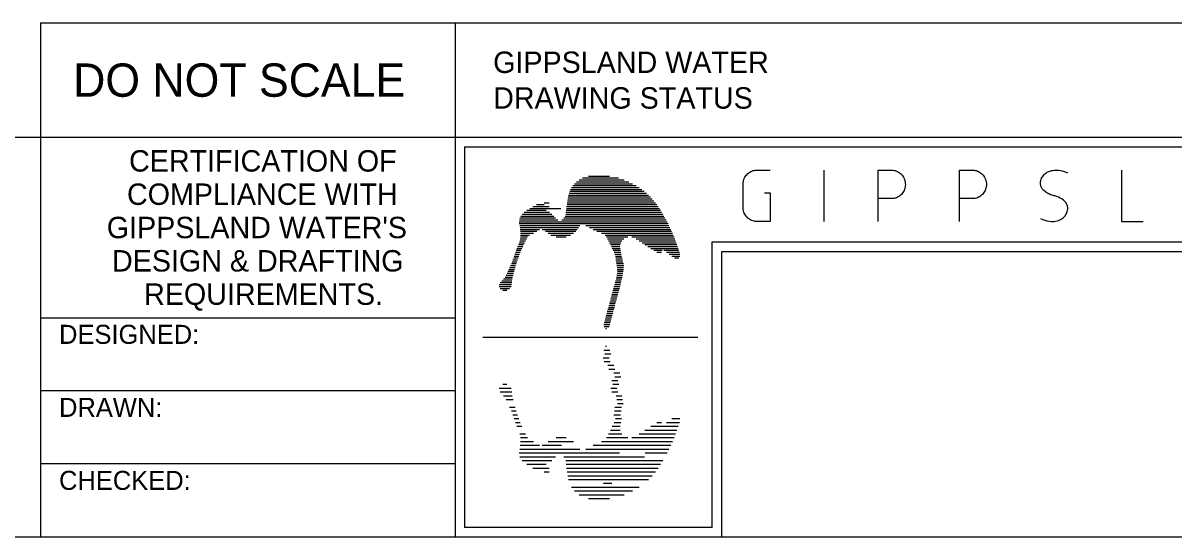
# Model space of a CAD drawing. Extents: x 0 to 841, y 0 to 594.
# Drawn here: x 590.7 to 711.5, y 15 to 69 of the extents above; entities that cross this region are included whole.
import ezdxf

# ---------------------------------------------------------------- set-up
doc = ezdxf.new("R2010")
doc.units = 0
doc.layers.add('A1BORDER', color=7, linetype='Continuous')

msp = doc.modelspace()

# ---------------------------------------------------------------- linework, layer by layer
at = {"layer": 'A1BORDER'}
for p, q in [((592.5, 69), (592.5, 15)), ((592.5, 69), (829, 69)), ((636, 69), (636, 15)), ((28, 57), (829, 57)), ((637, 56), (788, 56)), ((637, 56), (637, 16)), ((648.53, 52.12), (654.64, 52.12)), ((648.74, 52.32), (654.24, 52.32)), ((649.02, 52.52), (653.76, 52.52)), ((649.39, 52.72), (653.15, 52.72)), ((650.01, 52.92), (652.2, 52.92)), ((647.91, 50.92), (656.3, 50.92)), ((647.96, 51.12), (656.08, 51.12)), ((648.03, 51.32), (655.85, 51.32)), ((648.12, 51.52), (655.59, 51.52)), ((648.23, 51.72), (655.31, 51.72)), ((648.37, 51.92), (655, 51.92)), ((644.18, 49.72), (645.89, 49.72)), ((644.54, 49.92), (645.36, 49.92)), ((645.37, 50.12), (645.86, 50.12)), ((647.71, 49.72), (657.31, 49.72)), ((647.75, 49.92), (657.17, 49.92)), ((647.78, 50.12), (657.02, 50.12)), ((647.81, 50.32), (656.86, 50.32)), ((647.85, 50.52), (656.69, 50.52)), ((647.88, 50.72), (656.5, 50.72)), ((642.75, 48.32), (646.79, 48.32)), ((642.81, 48.52), (646.55, 48.52)), ((642.9, 48.72), (646.37, 48.72)), ((643.04, 48.92), (646.16, 48.92)), ((643.26, 49.12), (645.9, 49.12)), ((643.54, 49.32), (645.57, 49.32)), ((643.85, 49.52), (647.09, 49.52)), ((647.19, 48.32), (658.14, 48.32)), ((647.42, 48.52), (658.03, 48.52)), ((647.54, 48.72), (657.92, 48.72)), ((647.61, 48.92), (657.8, 48.92)), ((647.63, 49.12), (657.68, 49.12)), ((647.66, 49.32), (657.57, 49.32)), ((647.69, 49.52), (657.44, 49.52)), ((642.73, 48.12), (658.25, 48.12)), ((642.74, 47.92), (658.35, 47.92)), ((642.79, 47.72), (649.08, 47.72)), ((642.83, 47.52), (648.95, 47.52)), ((642.85, 47.31), (644.88, 47.31)), ((642.87, 47.12), (644.57, 47.12)), ((645.14, 47.31), (648.83, 47.31)), ((645.49, 47.12), (648.67, 47.12)), ((649.72, 47.72), (658.45, 47.72)), ((650.12, 47.52), (658.55, 47.52)), ((650.48, 47.31), (658.64, 47.31)), ((650.87, 47.12), (658.73, 47.12)), ((642.72, 45.92), (643.3, 45.92)), ((642.79, 46.12), (643.4, 46.12)), ((642.84, 46.32), (643.5, 46.32)), ((642.87, 46.52), (643.6, 46.52)), ((642.88, 46.92), (644.23, 46.92)), ((642.88, 46.72), (643.83, 46.72)), ((645.76, 46.92), (648.42, 46.92)), ((646.05, 46.72), (648.11, 46.72)), ((646.62, 46.52), (647.67, 46.52)), ((651.36, 46.92), (658.82, 46.92)), ((651.76, 46.72), (658.9, 46.72)), ((651.88, 46.52), (654.15, 46.52)), ((651.99, 46.32), (653.71, 46.32)), ((652.1, 46.12), (653.52, 46.12)), ((652.2, 45.92), (653.4, 45.92)), ((654.57, 46.52), (658.99, 46.52)), ((655, 46.32), (659.07, 46.32)), ((655.31, 46.12), (659.14, 46.12)), ((655.62, 45.92), (659.22, 45.92)), ((663, 46), (788, 46)), ((663, 16), (663, 46)), ((642.28, 44.72), (642.76, 44.72)), ((642.35, 44.92), (642.83, 44.92)), ((642.43, 45.12), (642.9, 45.12)), ((642.5, 45.32), (643, 45.32)), ((642.57, 45.52), (643.1, 45.52)), ((642.65, 45.72), (643.2, 45.72)), ((652.31, 45.72), (653.33, 45.72)), ((652.41, 45.52), (653.31, 45.52)), ((652.5, 45.32), (653.34, 45.32)), ((652.6, 45.12), (653.38, 45.12)), ((652.69, 44.92), (653.41, 44.92)), ((652.78, 44.72), (653.44, 44.72)), ((655.93, 45.72), (659.29, 45.72)), ((656.24, 45.52), (659.35, 45.52)), ((656.55, 45.32), (659.42, 45.32)), ((656.86, 45.12), (657.74, 45.12)), ((657.17, 44.92), (657.68, 44.92)), ((657.51, 44.72), (657.54, 44.72)), ((657.91, 45.12), (659.48, 45.12)), ((658.19, 44.92), (659.54, 44.92)), ((658.47, 44.72), (659.59, 44.72)), ((664, 45), (829, 45)), ((664, 15), (664, 45)), ((641.82, 43.51), (642.35, 43.51)), ((641.91, 43.72), (642.41, 43.72)), ((641.99, 43.92), (642.48, 43.92)), ((642.06, 44.12), (642.55, 44.12)), ((642.13, 44.32), (642.62, 44.32)), ((642.21, 44.52), (642.69, 44.52)), ((652.83, 44.52), (653.48, 44.52)), ((652.86, 44.32), (653.53, 44.32)), ((652.89, 44.12), (653.57, 44.12)), ((652.91, 43.92), (653.62, 43.92)), ((652.94, 43.72), (653.67, 43.72)), ((652.97, 43.51), (653.71, 43.51)), ((658.75, 44.52), (659.58, 44.52)), ((659.02, 44.32), (659.47, 44.32)), ((641.25, 42.31), (642.04, 42.31)), ((641.37, 42.52), (642.09, 42.52)), ((641.46, 42.72), (642.15, 42.72)), ((641.55, 42.92), (642.2, 42.92)), ((641.64, 43.12), (642.25, 43.12)), ((641.73, 43.32), (642.3, 43.32)), ((652.95, 42.31), (653.53, 42.31)), ((652.99, 42.52), (653.57, 42.52)), ((653, 43.32), (653.69, 43.32)), ((653.02, 43.12), (653.67, 43.12)), ((653.03, 42.72), (653.61, 42.72)), ((653.05, 42.92), (653.64, 42.92)), ((640.62, 41.32), (641.88, 41.32)), ((640.63, 41.52), (641.93, 41.52)), ((640.72, 41.12), (641.73, 41.12)), ((640.73, 41.72), (641.95, 41.72)), ((640.9, 41.92), (641.97, 41.92)), ((641.1, 42.12), (642, 42.12)), ((652.63, 41.12), (653.26, 41.12)), ((652.68, 41.32), (653.31, 41.32)), ((652.74, 41.52), (653.37, 41.52)), ((652.79, 41.72), (653.41, 41.72)), ((652.85, 41.92), (653.45, 41.92)), ((652.9, 42.12), (653.49, 42.12)), ((641.03, 40.92), (641.43, 40.92)), ((652.3, 39.92), (652.93, 39.92)), ((652.36, 40.12), (652.99, 40.12)), ((652.41, 40.32), (653.04, 40.32)), ((652.47, 40.52), (653.1, 40.52)), ((652.52, 40.72), (653.15, 40.72)), ((652.57, 40.92), (653.2, 40.92)), ((651.98, 38.72), (652.61, 38.72)), ((652.03, 38.92), (652.66, 38.92)), ((652.09, 39.12), (652.72, 39.12)), ((652.14, 39.32), (652.77, 39.32)), ((652.2, 39.52), (652.82, 39.52)), ((652.25, 39.72), (652.88, 39.72)), ((636, 38), (592.5, 38)), ((651.65, 37.52), (652.28, 37.52)), ((651.71, 37.72), (652.34, 37.72)), ((651.76, 37.92), (652.39, 37.92)), ((651.82, 38.12), (652.44, 38.12)), ((651.87, 38.32), (652.5, 38.32)), ((651.92, 38.52), (652.55, 38.52)), ((651.63, 37.32), (652.23, 37.32)), ((651.64, 37.12), (652.17, 37.12)), ((651.79, 36.92), (651.9, 36.92)), ((638.93, 35.98), (661.47, 35.98)), ((651.79, 35.04), (651.9, 35.04)), ((651.54, 33.84), (652.17, 33.84)), ((651.63, 34.64), (652.23, 34.64)), ((651.71, 34.24), (652.34, 34.24)), ((651.65, 33.44), (652.28, 33.44)), ((652.03, 33.04), (652.66, 33.04)), ((652.14, 32.64), (652.77, 32.64)), ((652.47, 31.44), (653.1, 31.44)), ((652.66, 32.24), (653.29, 32.24)), ((652.77, 31.84), (653.4, 31.84)), ((636, 30.34), (592.5, 30.34)), ((640.62, 30.64), (641.88, 30.64)), ((640.73, 30.24), (641.95, 30.24)), ((641.03, 31.04), (641.43, 31.04)), ((652.34, 30.64), (652.97, 30.64)), ((652.45, 30.24), (653.07, 30.24)), ((652.57, 31.04), (653.2, 31.04)), ((641.1, 29.84), (642, 29.84)), ((641.37, 29.44), (642.09, 29.44)), ((652.9, 29.84), (653.49, 29.84)), ((652.99, 29.44), (653.57, 29.44)), ((653.05, 29.04), (653.64, 29.04)), ((641.73, 28.64), (642.3, 28.64)), ((641.91, 28.24), (642.41, 28.24)), ((642.06, 27.84), (642.55, 27.84)), ((652.66, 27.84), (653.35, 27.84)), ((652.72, 28.24), (653.44, 28.24)), ((652.77, 28.64), (653.46, 28.64)), ((642.21, 27.44), (642.69, 27.44)), ((642.35, 27.04), (642.83, 27.04)), ((642.5, 26.64), (643, 26.64)), ((652.5, 26.64), (653.34, 26.64)), ((652.69, 27.04), (653.41, 27.04)), ((652.83, 27.44), (653.48, 27.44)), ((656.55, 26.64), (659.42, 26.64)), ((657.17, 27.04), (657.68, 27.04)), ((658.19, 27.04), (659.54, 27.04)), ((658.75, 27.44), (659.58, 27.44)), ((642.79, 25.84), (643.4, 25.84)), ((642.87, 25.44), (643.6, 25.44)), ((646.62, 25.44), (647.67, 25.44)), ((651.88, 25.44), (654.15, 25.44)), ((652.1, 25.84), (653.52, 25.84)), ((652.31, 26.24), (653.33, 26.24)), ((654.57, 25.44), (658.99, 25.44)), ((655.31, 25.84), (659.14, 25.84)), ((655.93, 26.24), (659.29, 26.24)), ((642.79, 24.24), (649.08, 24.24)), ((642.85, 24.65), (644.88, 24.65)), ((642.88, 25.04), (644.23, 25.04)), ((645.14, 24.65), (647.18, 24.65)), ((645.76, 25.04), (648.42, 25.04)), ((649.72, 24.24), (658.45, 24.24)), ((650.48, 24.65), (658.64, 24.65)), ((651.36, 25.04), (658.82, 25.04)), ((642.73, 23.84), (653.27, 23.84)), ((642.81, 23.44), (646.55, 23.44)), ((643.04, 23.04), (646.16, 23.04)), ((647.42, 23.44), (655.89, 23.44)), ((647.61, 23.04), (657.8, 23.04)), ((655.94, 23.84), (658.25, 23.84)), ((636, 22.67), (592.5, 22.67)), ((643.54, 22.64), (645.57, 22.64)), ((644.18, 22.24), (645.89, 22.24)), ((645.37, 21.84), (645.86, 21.84)), ((647.66, 22.64), (657.57, 22.64)), ((647.71, 22.24), (657.31, 22.24)), ((647.78, 21.84), (657.02, 21.84)), ((647.85, 21.44), (656.69, 21.44)), ((647.91, 21.04), (656.3, 21.04)), ((651.57, 20.64), (652.44, 20.64)), ((648.23, 20.24), (655.31, 20.24)), ((648.53, 19.84), (654.64, 19.84)), ((649.02, 19.44), (653.76, 19.44)), ((650.01, 19.04), (652.2, 19.04)), ((663, 16), (637, 16)), ((829, 15), (28, 15))]:
    msp.add_line(p, q, dxfattribs=at)
for points in [[(668.49, 51.15), (669.06, 51.15), (669.06, 48.16), (667.64, 48.16), (667.51, 48.16), (667.39, 48.18), (667.28, 48.21), (667.15, 48.25), (667.04, 48.3), (666.93, 48.36), (666.82, 48.43), (666.73, 48.51), (666.64, 48.6), (666.55, 48.7), (666.48, 48.8), (666.41, 48.91), (666.35, 49.02), (666.31, 49.14), (666.27, 49.27), (666.24, 49.39), (666.22, 49.52), (666.22, 49.66), (666.22, 52.05), (666.22, 52.18), (666.24, 52.31), (666.27, 52.43), (666.31, 52.56), (666.35, 52.67), (666.41, 52.79), (666.48, 52.9), (666.55, 53), (666.64, 53.1), (666.73, 53.19), (666.82, 53.27), (666.93, 53.34), (667.04, 53.4), (667.15, 53.45), (667.28, 53.49), (667.39, 53.52), (667.51, 53.54), (667.64, 53.54), (669.06, 53.54)], [(674.74, 48.16), (674.74, 53.54)], [(680.42, 48.16), (680.42, 53.54), (681.84, 53.54), (681.96, 53.54), (682.08, 53.52), (682.2, 53.49), (682.32, 53.45), (682.43, 53.4), (682.54, 53.34), (682.65, 53.27), (682.74, 53.19), (682.84, 53.1), (682.92, 53), (682.99, 52.9), (683.06, 52.79), (683.12, 52.67), (683.17, 52.56), (683.21, 52.43), (683.23, 52.31), (683.25, 52.18), (683.26, 52.05), (683.25, 51.91), (683.23, 51.78), (683.21, 51.66), (683.17, 51.53), (683.12, 51.42), (683.06, 51.3), (682.99, 51.19), (682.92, 51.09), (682.84, 50.99), (682.74, 50.9), (682.65, 50.82), (682.54, 50.75), (682.43, 50.69), (682.32, 50.64), (682.2, 50.6), (682.08, 50.57), (681.96, 50.55), (681.84, 50.55), (680.42, 50.55)], [(688.93, 48.16), (688.93, 53.54), (690.35, 53.54), (690.47, 53.54), (690.59, 53.52), (690.71, 53.49), (690.83, 53.45), (690.94, 53.4), (691.05, 53.34), (691.16, 53.27), (691.26, 53.19), (691.35, 53.1), (691.43, 53), (691.51, 52.9), (691.57, 52.79), (691.63, 52.67), (691.68, 52.56), (691.72, 52.43), (691.75, 52.31), (691.76, 52.18), (691.77, 52.05), (691.76, 51.91), (691.75, 51.78), (691.72, 51.66), (691.68, 51.53), (691.63, 51.42), (691.57, 51.3), (691.51, 51.19), (691.43, 51.09), (691.35, 50.99), (691.26, 50.9), (691.16, 50.82), (691.05, 50.75), (690.94, 50.69), (690.83, 50.64), (690.71, 50.6), (690.59, 50.57), (690.47, 50.55), (690.35, 50.55), (688.93, 50.55)], [(697.45, 48.46), (697.67, 48.36), (697.9, 48.27), (698.12, 48.21), (698.36, 48.17), (698.6, 48.16), (698.84, 48.16), (698.87, 48.16), (699.03, 48.18), (699.18, 48.21), (699.33, 48.26), (699.48, 48.32), (699.62, 48.4), (699.72, 48.46), (699.81, 48.53), (699.9, 48.61), (699.98, 48.69), (700.05, 48.78), (700.11, 48.88), (700.17, 48.99), (700.22, 49.09), (700.25, 49.21), (700.28, 49.32), (700.29, 49.36), (700.3, 49.44), (700.3, 49.52), (700.3, 49.61), (700.29, 49.69), (700.27, 49.77), (700.25, 49.86), (700.22, 49.93), (700.18, 50.01), (700.14, 50.09), (700.09, 50.15), (700.04, 50.21), (700.01, 50.25), (699.85, 50.39), (699.69, 50.51), (699.52, 50.61), (699.34, 50.7), (699.15, 50.78), (698.95, 50.83), (698.87, 50.85), (698.68, 50.9), (698.49, 50.96), (698.3, 51.04), (698.12, 51.14), (697.96, 51.26), (697.8, 51.39), (697.73, 51.45), (697.67, 51.51), (697.62, 51.57), (697.58, 51.64), (697.53, 51.71), (697.5, 51.79), (697.47, 51.87), (697.46, 51.95), (697.44, 52.04), (697.43, 52.12), (697.43, 52.21), (697.44, 52.29), (697.45, 52.35), (697.47, 52.46), (697.51, 52.58), (697.55, 52.69), (697.61, 52.79), (697.67, 52.89), (697.74, 52.99), (697.82, 53.07), (697.9, 53.15), (697.99, 53.23), (698.02, 53.24), (698.15, 53.33), (698.3, 53.4), (698.44, 53.45), (698.6, 53.5), (698.75, 53.52), (698.87, 53.54), (699.11, 53.55), (699.35, 53.53), (699.58, 53.49), (699.82, 53.43), (700.04, 53.35), (700.27, 53.25)], [(705.96, 53.54), (705.96, 48.16), (708.23, 48.16)]]:
    msp.add_lwpolyline(points, dxfattribs=at)

# ---------------------------------------------------------------- texts
for s, height, p in [('GIPPSLAND WATER', 2.25, (640, 63.75)), ('DO NOT SCALE', 3.5, (595.92, 61.25)), ('DRAWING STATUS', 2.25, (640, 60)), ('CERTIFICATION OF', 2.25, (601.79, 53.39)), ('COMPLIANCE WITH', 2.25, (601.57, 49.89)), ("GIPPSLAND WATER'S", 2.25, (599.45, 46.39)), ('DESIGN & DRAFTING', 2.25, (600, 42.89)), ('REQUIREMENTS.', 2.25, (603.37, 39.39)), ('DESIGNED:', 2, (594.44, 35.29)), ('DRAWN:', 2, (594.44, 27.62)), ('CHECKED:', 2, (594.44, 19.95))]:
    msp.add_text(s, height=height, dxfattribs=at).set_placement(p)

doc.saveas('drawing.dxf')
